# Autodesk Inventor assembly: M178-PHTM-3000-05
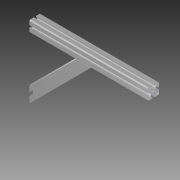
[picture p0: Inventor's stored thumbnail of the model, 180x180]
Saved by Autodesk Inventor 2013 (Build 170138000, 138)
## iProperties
Created: 2004-11
Part Number: M178-PHTM-3000-05
Document SubType Name: Assembly
Designer: Autodesk, Inc.
Manufacturer: Standard
Standards Organization: Custom
Description: PHANTOM, HUTCH OVERHANG
Mass: 1298.13 g
Surface Area: 3322.27 cm^2
Volume: 458.284 cm^3
Density: 2.83259 g/cm^3
CAGE: 1LJX3
Dept. ID: Product Design
Description #2: ---
Finish #1: ---
Finish #2: ---
Material ID: ---
Project Number: ---
Author: Autodesk, Inc.
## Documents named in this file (9)
- Z:\_DATEN\Test Station\Components\M178-3000 Overhange Phantom.iam
- Z:\_DATEN\Test Station\Components\M178-3003.ipt
- Z:\_DATEN\Test Station\Components\M178-3004.ipt
- Z:\_DATEN\Test Station\Components\20-004.iam
- Z:\_DATEN\Test Station\Components\20-058.ipt
- Z:\_DATEN\Test Station\Components\24-120-8.ipt
- C:\Users\kelleyb.ADS\Desktop\Samples MIGRATED 2009 224 RTM_1\Standard Parts\Test Station Content\Extrusions\40 Series Profiles.ipt
- C:\Users\kelleyb.ADS\Desktop\Samples MIGRATED 2009 224 RTM_1\Standard Parts\Test Station Content\Fastners\2X-YYY-ZZ IPS Screws.ipt
- C:\Users\kelleyb.ADS\Desktop\Samples MIGRATED 2009 224 RTM_1\Standard Parts\Test Station Content\Fastners\20-XXX TSlot Nuts.ipt
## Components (7 placed, 5 different names)
1. M178-3003:1 — Insert:1, Angle:1, Mate:1, Flush:1, Flush:2
2. M178-3004:2 — Mate:1, Flush:1, Flush:2, Insert:2, Insert:3, Mate:3, Mate:4, Angle:2, Angle:3
3. 20-004:1 [sub-assembly] — Insert:1, Angle:1
4. 24-120-8:1 — Insert:2, Mate:2
5. 24-120-8:2 — Insert:3, Mate:5
6. 20-058:1 — Mate:2, Mate:3, Angle:3
7. 20-058:2 — Mate:4, Mate:5, Angle:2
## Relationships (13: Mate 5, Insert 3, Angle 3, Flush 2)
- Insert:1: M178-3003:1 ↔ 20-004:1
- Angle:1: M178-3003:1 ↔ 20-004:1
- Mate:1: M178-3003:1 ↔ M178-3004:2
- Flush:1: M178-3003:1 ↔ M178-3004:2
- Flush:2: M178-3003:1 ↔ M178-3004:2
- Insert:2: M178-3004:2 ↔ 24-120-8:1
- Insert:3: M178-3004:2 ↔ 24-120-8:2
- Mate:2: 24-120-8:1 ↔ 20-058:1
- Mate:3: M178-3004:2 ↔ 20-058:1
- Mate:4: M178-3004:2 ↔ 20-058:2
- Mate:5: 24-120-8:2 ↔ 20-058:2
- Angle:2: M178-3004:2 ↔ 20-058:2
- Angle:3: M178-3004:2 ↔ 20-058:1
